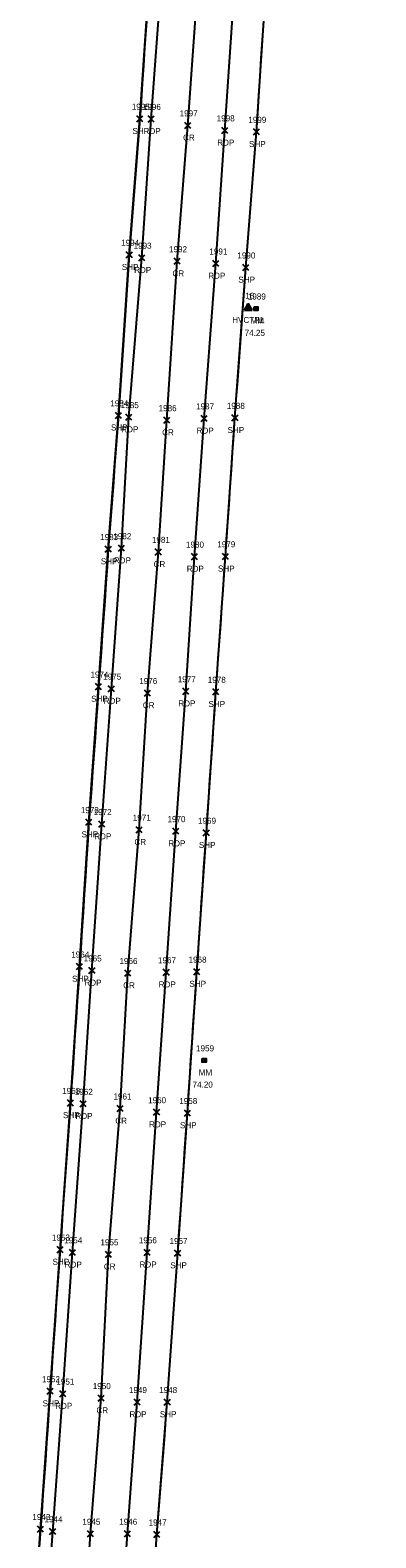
# Model space of a CAD drawing. Extents: x 1688195 to 1692013, y 424605 to 441234.
# Drawn here: x 1690595.7 to 1690709.9, y 436148.3 to 436646.5 of the extents above; entities that cross this region are included whole.
import ezdxf

# ---------------------------------------------------------------- set-up
doc = ezdxf.new("R2010")
doc.units = 0
for name, color, linetype in [('C_A', 7, 'Continuous'), ('C_I', 7, 'Continuous'), ('CPSM', 7, 'Continuous'), ('LSOGP', 7, 'Continuous'), ('P_A', 7, 'Continuous'), ('P_I', 7, 'Continuous'), ('P_TIC', 7, 'Continuous'), ('PET', 7, 'Continuous'), ('PRC', 7, 'Continuous'), ('PSP', 7, 'Continuous'), ('S_A', 7, 'Continuous'), ('S_C', 7, 'Continuous'), ('S_I', 7, 'Continuous'), ('SRM', 7, 'Continuous')]:
    doc.layers.add(name, color=color, linetype=linetype)

msp = doc.modelspace()

# ---------------------------------------------------------------- linework, layer by layer
at = {"layer": 'CPSM'}
for p, q in [((1690666.48, 436554.06), (1690667.73, 436556.22)), ((1690666.48, 436554.06), (1690667.73, 436554.78)), ((1690666.48, 436554.06), (1690668.98, 436554.06)), ((1690668.98, 436554.06), (1690667.73, 436556.22)), ((1690667.73, 436554.78), (1690667.73, 436556.22)), ((1690667.73, 436554.78), (1690667.73, 436554.78)), ((1690667.73, 436554.78), (1690668.98, 436554.06))]:
    msp.add_line(p, q, dxfattribs=at)
at = {"layer": 'LSOGP'}
for points in [[(1690634.29, 436652.37), (1690633.89, 436646.51), (1690633.5, 436640.66), (1690633.11, 436634.8), (1690632.72, 436628.94), (1690632.33, 436623.09), (1690631.94, 436617.23), (1690631.5, 436611.61), (1690631.06, 436606), (1690630.62, 436600.38), (1690630.18, 436594.76), (1690629.74, 436589.14), (1690629.3, 436583.53), (1690628.87, 436577.91), (1690628.43, 436572.29), (1690627.98, 436565.66), (1690627.53, 436559.03), (1690627.08, 436552.4), (1690626.63, 436545.77), (1690626.18, 436539.14), (1690625.73, 436532.51), (1690625.29, 436525.87), (1690624.84, 436519.24), (1690624.42, 436513.72), (1690624, 436508.19), (1690623.58, 436502.66), (1690623.17, 436497.13), (1690622.75, 436491.6), (1690622.33, 436486.08), (1690621.91, 436480.55), (1690621.49, 436475.02), (1690621.09, 436469.34), (1690620.69, 436463.66), (1690620.29, 436457.98), (1690619.89, 436452.3), (1690619.49, 436446.62), (1690619.09, 436440.94), (1690618.69, 436435.26), (1690618.29, 436429.58), (1690617.89, 436423.98), (1690617.49, 436418.38), (1690617.1, 436412.78), (1690616.7, 436407.18), (1690616.3, 436401.58), (1690615.9, 436395.98), (1690615.5, 436390.38), (1690615.1, 436384.78), (1690614.71, 436378.82), (1690614.32, 436372.85), (1690613.93, 436366.89), (1690613.54, 436360.92), (1690613.15, 436354.96), (1690612.76, 436348.99), (1690612.37, 436343.03), (1690611.61, 436331.43), (1690611.23, 436325.79), (1690610.85, 436320.16), (1690610.48, 436314.52), (1690610.1, 436308.89), (1690609.73, 436303.26), (1690609.35, 436297.62), (1690608.98, 436291.99), (1690608.55, 436285.93), (1690608.12, 436279.87), (1690607.69, 436273.81), (1690607.26, 436267.75), (1690606.83, 436261.7), (1690606.41, 436255.64), (1690605.98, 436249.58), (1690605.55, 436243.52), (1690605.14, 436237.67), (1690604.73, 436231.82), (1690604.32, 436225.97), (1690603.91, 436220.12), (1690603.5, 436214.27), (1690603.09, 436208.42), (1690602.68, 436202.58), (1690602.27, 436196.73), (1690601.88, 436191.03), (1690601.48, 436185.34), (1690601.08, 436179.65), (1690600.69, 436173.95), (1690600.29, 436168.26), (1690599.89, 436162.57), (1690599.5, 436156.87), (1690598.67, 436145.19)], [(1690637.08, 436143.21), (1690637.49, 436149.36), (1690637.93, 436154.83), (1690638.36, 436160.31), (1690638.8, 436165.78), (1690639.24, 436171.25), (1690639.67, 436176.72), (1690640.11, 436182.19), (1690640.54, 436187.66), (1690640.98, 436193.14), (1690641.41, 436199.29), (1690641.84, 436205.44), (1690642.27, 436211.6), (1690642.7, 436217.75), (1690643.12, 436223.91), (1690643.55, 436230.06), (1690643.98, 436236.21), (1690644.41, 436242.37), (1690644.81, 436248.15), (1690645.22, 436253.94), (1690645.62, 436259.72), (1690646.02, 436265.51), (1690646.42, 436271.29), (1690646.82, 436277.08), (1690647.22, 436282.86), (1690647.62, 436288.65), (1690648.01, 436294.49), (1690648.4, 436300.33), (1690648.79, 436306.17), (1690649.18, 436312.01), (1690649.57, 436317.85), (1690649.96, 436323.7), (1690650.35, 436329.54), (1690650.74, 436335.38), (1690651.14, 436341.11), (1690651.53, 436346.85), (1690651.92, 436352.59), (1690652.31, 436358.32), (1690652.7, 436364.06), (1690653.1, 436369.8), (1690653.49, 436375.53), (1690653.88, 436381.27), (1690654.27, 436387.09), (1690654.67, 436392.91), (1690655.07, 436398.74), (1690655.46, 436404.56), (1690655.86, 436410.38), (1690656.25, 436416.21), (1690656.65, 436422.03), (1690657.04, 436427.85), (1690657.44, 436433.45), (1690657.83, 436439.04), (1690658.22, 436444.64), (1690658.61, 436450.24), (1690659.01, 436455.83), (1690659.4, 436461.43), (1690659.79, 436467.02), (1690660.19, 436472.62), (1690660.58, 436478.34), (1690660.97, 436484.06), (1690661.37, 436489.79), (1690661.76, 436495.51), (1690662.16, 436501.23), (1690662.55, 436506.95), (1690662.94, 436512.68), (1690663.34, 436518.4), (1690663.78, 436524.61), (1690664.23, 436530.82), (1690664.68, 436537.03), (1690665.13, 436543.25), (1690665.57, 436549.46), (1690666.02, 436555.67), (1690666.47, 436561.88), (1690666.91, 436568.09), (1690667.35, 436573.69), (1690667.8, 436579.3), (1690668.24, 436584.9), (1690668.68, 436590.5), (1690669.12, 436596.1), (1690669.56, 436601.7), (1690670, 436607.3), (1690670.44, 436612.91), (1690670.84, 436619), (1690671.24, 436625.09), (1690671.64, 436631.19), (1690672.04, 436637.28), (1690672.44, 436643.37), (1690672.84, 436649.47)]]:
    msp.add_lwpolyline(points, dxfattribs=at)
at = {"layer": 'P_TIC'}
for points in [[(1690630.94, 436616.23), (1690632.94, 436618.23)], [(1690632.94, 436616.23), (1690630.94, 436618.23)], [(1690634.65, 436616.18), (1690636.65, 436618.18)], [(1690636.65, 436616.18), (1690634.65, 436618.18)], [(1690646.75, 436614.04), (1690648.75, 436616.04)], [(1690648.75, 436614.04), (1690646.75, 436616.04)], [(1690658.98, 436612.4), (1690660.98, 436614.4)], [(1690660.98, 436612.4), (1690658.98, 436614.4)], [(1690669.44, 436611.91), (1690671.44, 436613.91)], [(1690671.44, 436611.91), (1690669.44, 436613.91)], [(1690627.43, 436571.29), (1690629.43, 436573.29)], [(1690629.43, 436571.29), (1690627.43, 436573.29)], [(1690631.52, 436570.32), (1690633.52, 436572.32)], [(1690633.52, 436570.32), (1690631.52, 436572.32)], [(1690643.24, 436569.17), (1690645.24, 436571.17)], [(1690645.24, 436569.17), (1690643.24, 436571.17)], [(1690656.01, 436568.4), (1690658.01, 436570.4)], [(1690658.01, 436568.4), (1690656.01, 436570.4)], [(1690665.91, 436567.09), (1690667.91, 436569.09)], [(1690667.91, 436567.09), (1690665.91, 436569.09)], [(1690623.84, 436518.24), (1690625.84, 436520.24)], [(1690625.84, 436518.24), (1690623.84, 436520.24)], [(1690627.28, 436517.63), (1690629.28, 436519.63)], [(1690629.28, 436517.63), (1690627.28, 436519.63)], [(1690639.85, 436516.62), (1690641.85, 436518.62)], [(1690641.85, 436516.62), (1690639.85, 436518.62)], [(1690652.18, 436517.22), (1690654.18, 436519.22)], [(1690654.18, 436517.22), (1690652.18, 436519.22)], [(1690662.34, 436517.4), (1690664.34, 436519.4)], [(1690664.34, 436517.4), (1690662.34, 436519.4)], [(1690620.49, 436474.02), (1690622.49, 436476.02)], [(1690622.49, 436474.02), (1690620.49, 436476.02)], [(1690624.84, 436474.31), (1690626.84, 436476.31)], [(1690626.84, 436474.31), (1690624.84, 436476.31)], [(1690637.02, 436473.09), (1690639.02, 436475.09)], [(1690639.02, 436473.09), (1690637.02, 436475.09)], [(1690648.93, 436471.54), (1690650.93, 436473.54)], [(1690650.93, 436471.54), (1690648.93, 436473.54)], [(1690659.19, 436471.62), (1690661.19, 436473.62)], [(1690661.19, 436471.62), (1690659.19, 436473.62)], [(1690617.29, 436428.58), (1690619.29, 436430.58)], [(1690619.29, 436428.58), (1690617.29, 436430.58)], [(1690621.49, 436427.9), (1690623.49, 436429.9)], [(1690623.49, 436427.9), (1690621.49, 436429.9)], [(1690633.46, 436426.45), (1690635.46, 436428.45)], [(1690635.46, 436426.45), (1690633.46, 436428.45)], [(1690646.13, 436427.04), (1690648.13, 436429.04)], [(1690648.13, 436427.04), (1690646.13, 436429.04)], [(1690656.04, 436426.85), (1690658.04, 436428.85)], [(1690658.04, 436426.85), (1690656.04, 436428.85)], [(1690614.1, 436383.78), (1690616.1, 436385.78)], [(1690616.1, 436383.78), (1690614.1, 436385.78)], [(1690618.34, 436383.14), (1690620.34, 436385.14)], [(1690620.34, 436383.14), (1690618.34, 436385.14)], [(1690630.69, 436381.27), (1690632.69, 436383.27)], [(1690632.69, 436381.27), (1690630.69, 436383.27)], [(1690642.82, 436380.8), (1690644.82, 436382.8)], [(1690644.82, 436380.8), (1690642.82, 436382.8)], [(1690652.88, 436380.27), (1690654.88, 436382.27)], [(1690654.88, 436380.27), (1690652.88, 436382.27)], [(1690610.98, 436336.06), (1690612.98, 436338.06)], [(1690612.98, 436336.06), (1690610.98, 436338.06)], [(1690615.1, 436334.77), (1690617.1, 436336.77)], [(1690617.1, 436334.77), (1690615.1, 436336.77)], [(1690626.98, 436333.91), (1690628.98, 436335.91)], [(1690628.98, 436333.91), (1690626.98, 436335.91)], [(1690639.65, 436334.17), (1690641.65, 436336.17)], [(1690641.65, 436334.17), (1690639.65, 436336.17)], [(1690649.74, 436334.38), (1690651.74, 436336.38)], [(1690651.74, 436334.38), (1690649.74, 436336.38)], [(1690607.98, 436290.99), (1690609.98, 436292.99)], [(1690609.98, 436290.99), (1690607.98, 436292.99)], [(1690612.15, 436290.7), (1690614.15, 436292.7)], [(1690614.15, 436290.7), (1690612.15, 436292.7)], [(1690624.37, 436289.15), (1690626.37, 436291.15)], [(1690626.37, 436289.15), (1690624.37, 436291.15)], [(1690636.46, 436287.92), (1690638.46, 436289.92)], [(1690638.46, 436287.92), (1690636.46, 436289.92)], [(1690646.62, 436287.65), (1690648.62, 436289.65)], [(1690648.62, 436287.65), (1690646.62, 436289.65)], [(1690604.55, 436242.52), (1690606.55, 436244.52)], [(1690606.55, 436242.52), (1690604.55, 436244.52)], [(1690608.62, 436241.61), (1690610.62, 436243.61)], [(1690610.62, 436241.61), (1690608.62, 436243.61)], [(1690620.58, 436240.95), (1690622.58, 436242.95)], [(1690622.58, 436240.95), (1690620.58, 436242.95)], [(1690633.33, 436241.62), (1690635.33, 436243.62)], [(1690635.33, 436241.62), (1690633.33, 436243.62)], [(1690643.41, 436241.37), (1690645.41, 436243.37)], [(1690645.41, 436241.37), (1690643.41, 436243.37)], [(1690601.27, 436195.73), (1690603.27, 436197.73)], [(1690603.27, 436195.73), (1690601.27, 436197.73)], [(1690605.45, 436194.92), (1690607.45, 436196.92)], [(1690607.45, 436194.92), (1690605.45, 436196.92)], [(1690618.14, 436193.44), (1690620.14, 436195.44)], [(1690620.14, 436193.44), (1690618.14, 436195.44)], [(1690630, 436192.14), (1690632, 436194.14)], [(1690632, 436192.14), (1690630, 436194.14)], [(1690639.98, 436192.14), (1690641.98, 436194.14)], [(1690641.98, 436192.14), (1690639.98, 436194.14)], [(1690598.1, 436150.18), (1690600.1, 436152.18)], [(1690600.1, 436150.18), (1690598.1, 436152.18)], [(1690602.11, 436149.42), (1690604.11, 436151.42)], [(1690604.11, 436149.42), (1690602.11, 436151.42)], [(1690614.61, 436148.6), (1690616.61, 436150.6)], [(1690616.61, 436148.6), (1690614.61, 436150.6)], [(1690626.83, 436148.61), (1690628.83, 436150.61)], [(1690628.83, 436148.61), (1690626.83, 436150.61)], [(1690636.49, 436148.36), (1690638.49, 436150.36)], [(1690638.49, 436148.36), (1690636.49, 436150.36)]]:
    msp.add_lwpolyline(points, dxfattribs=at)
at = {"layer": 'PET'}
for points in [[(1690599.8, 436103.13), (1690603.11, 436150.42), (1690606.45, 436195.92), (1690609.62, 436242.61), (1690613.15, 436291.7), (1690616.1, 436335.77), (1690619.34, 436384.14), (1690622.49, 436428.9), (1690625.84, 436475.31), (1690628.28, 436518.63), (1690632.52, 436571.32), (1690635.65, 436617.18), (1690639.02, 436663.31), (1690642.46, 436711.88), (1690645.52, 436755.73), (1690649.02, 436803.75), (1690652.27, 436851.26), (1690655.23, 436898.72), (1690658.96, 436945.13), (1690661.93, 436991.78), (1690665.8, 437037.84), (1690668.55, 437085.38), (1690672.22, 437133.51), (1690675.32, 437180.59)], [(1690624.3, 436100.17), (1690627.83, 436149.61), (1690631, 436193.14), (1690634.33, 436242.62), (1690637.46, 436288.92), (1690640.65, 436335.17), (1690643.82, 436381.8), (1690647.13, 436428.04), (1690649.93, 436472.54), (1690653.18, 436518.22), (1690657.01, 436569.4), (1690659.98, 436613.4), (1690663.31, 436662.09), (1690666.73, 436708.73), (1690670, 436753.83), (1690673.18, 436800.78), (1690676.66, 436849.03), (1690679.84, 436896.21), (1690683.52, 436944.48), (1690686.54, 436988.83), (1690689.86, 437035.4), (1690693.25, 437082.57), (1690696.48, 437132.39), (1690699.66, 437177.7)]]:
    msp.add_lwpolyline(points, dxfattribs=at)
at = {"layer": 'PRC'}
msp.add_lwpolyline([(1690612.37, 436101.96), (1690615.61, 436149.6), (1690619.14, 436194.44), (1690621.58, 436241.95), (1690625.37, 436290.15), (1690627.98, 436334.91), (1690631.69, 436382.27), (1690634.46, 436427.45), (1690638.02, 436474.09), (1690640.85, 436517.62), (1690644.24, 436570.17), (1690647.75, 436615.04), (1690651.12, 436662.81), (1690654.54, 436710.08), (1690657.74, 436755.06), (1690660.75, 436802.55), (1690664.33, 436850.21), (1690667.58, 436897.29), (1690670.81, 436944.27), (1690673.92, 436990), (1690677.36, 437036.96), (1690680.4, 437083.81), (1690683.84, 437132.47), (1690687.9, 437179.25)], dxfattribs=at)
at = {"layer": 'PSP'}
for points in [[(1690595.68, 436103.23), (1690599.1, 436151.18), (1690602.27, 436196.73), (1690605.55, 436243.52), (1690608.98, 436291.99), (1690611.98, 436337.06), (1690615.1, 436384.78), (1690618.29, 436429.58), (1690621.49, 436475.02), (1690624.84, 436519.24), (1690628.43, 436572.29), (1690631.94, 436617.23), (1690635.07, 436664.09), (1690638.1, 436712.12), (1690641.49, 436756.88), (1690644.68, 436803.77), (1690648.2, 436852.63), (1690651.28, 436898.94), (1690654.63, 436946.33), (1690657.71, 436992.3), (1690661.08, 437038.52), (1690664.37, 437085.75), (1690667.55, 437134.28), (1690670.88, 437180.54)], [(1690634.23, 436100.1), (1690637.49, 436149.36), (1690640.98, 436193.14), (1690644.41, 436242.37), (1690647.62, 436288.65), (1690650.74, 436335.38), (1690653.88, 436381.27), (1690657.04, 436427.85), (1690660.19, 436472.62), (1690663.34, 436518.4), (1690666.91, 436568.09), (1690670.44, 436612.91), (1690673.64, 436661.65), (1690677.16, 436708.74), (1690680.36, 436753.14), (1690683.38, 436799.8), (1690686.78, 436848.43), (1690688.77, 436896.68), (1690693.3, 436942.76), (1690696.54, 436989.07), (1690699.73, 437035.52), (1690703.25, 437082.34), (1690706.73, 437130.77), (1690709.86, 437177.48)]]:
    msp.add_lwpolyline(points, dxfattribs=at)
at = {"layer": 'SRM'}
for points in [[(1690669.66, 436555.14), (1690670.91, 436555.14), (1690670.91, 436553.89), (1690669.66, 436553.89)], [(1690652.54, 436306.71), (1690653.79, 436306.71), (1690653.79, 436305.46), (1690652.54, 436305.46)]]:
    msp.add_lwpolyline(points, close=True, dxfattribs=at)
for centre in [(1690670.28, 436554.52), (1690653.17, 436306.08)]:
    msp.add_circle(centre, 0.0833, dxfattribs=at)

# ---------------------------------------------------------------- texts
at = {"layer": 'C_A'}
msp.add_text('HVCTRL', height=2, dxfattribs=at).set_placement((1690662.42, 436549.78))
at = {"layer": 'C_I'}
msp.add_text('16', height=2, dxfattribs=at).set_placement((1690666.77, 436557.78))
at = {"layer": 'P_A'}
for s, p in [('SHP', (1690629.47, 436612.23)), ('RDP', (1690633.14, 436612.18)), ('CR', (1690646.18, 436610.04)), ('RDP', (1690657.47, 436608.4)), ('SHP', (1690667.98, 436607.91)), ('SHP', (1690625.96, 436567.29)), ('RDP', (1690630.01, 436566.32)), ('CR', (1690642.68, 436565.17)), ('RDP', (1690654.49, 436564.4)), ('SHP', (1690664.45, 436563.09)), ('SHP', (1690622.37, 436514.24)), ('RDP', (1690625.77, 436513.63)), ('CR', (1690639.28, 436512.62)), ('RDP', (1690650.67, 436513.22)), ('SHP', (1690660.87, 436513.4)), ('RDP', (1690623.32, 436470.31)), ('SHP', (1690619.03, 436470.02)), ('CR', (1690636.45, 436469.09)), ('RDP', (1690647.41, 436467.54)), ('SHP', (1690657.72, 436467.62)), ('SHP', (1690615.83, 436424.58)), ('RDP', (1690619.98, 436423.9)), ('CR', (1690632.89, 436422.45)), ('RDP', (1690644.62, 436423.04)), ('SHP', (1690654.58, 436422.85)), ('SHP', (1690612.64, 436379.78)), ('RDP', (1690616.83, 436379.14)), ('CR', (1690630.12, 436377.27)), ('RDP', (1690641.31, 436376.8)), ('SHP', (1690651.41, 436376.27)), ('SHP', (1690609.52, 436332.06)), ('RDP', (1690613.59, 436330.77)), ('CR', (1690626.41, 436329.91)), ('RDP', (1690638.14, 436330.17)), ('SHP', (1690648.28, 436330.38)), ('SHP', (1690606.51, 436286.99)), ('RDP', (1690610.64, 436286.7)), ('CR', (1690623.8, 436285.15)), ('RDP', (1690634.95, 436283.92)), ('SHP', (1690645.16, 436283.65)), ('SHP', (1690603.08, 436238.52)), ('RDP', (1690607.1, 436237.61)), ('CR', (1690620.02, 436236.95)), ('RDP', (1690631.82, 436237.62)), ('SHP', (1690641.95, 436237.37)), ('SHP', (1690599.81, 436191.73)), ('RDP', (1690603.94, 436190.92)), ('CR', (1690617.57, 436189.44)), ('RDP', (1690628.48, 436188.14)), ('SHP', (1690638.51, 436188.14))]:
    msp.add_text(s, height=2, dxfattribs=at).set_placement(p)
at = {"layer": 'P_I'}
for s, p in [('1995', (1690629.25, 436620.23)), ('1996', (1690632.9, 436620.18)), ('1997', (1690645.05, 436618.04)), ('1998', (1690657.29, 436616.4)), ('1999', (1690667.74, 436615.91)), ('1994', (1690625.73, 436575.29)), ('1993', (1690629.83, 436574.32)), ('1992', (1690641.55, 436573.17)), ('1991', (1690654.88, 436572.4)), ('1990', (1690664.13, 436571.09)), ('1984', (1690622.14, 436522.24)), ('1985', (1690625.59, 436521.63)), ('1986', (1690638.1, 436520.62)), ('1987', (1690650.48, 436521.22)), ('1988', (1690660.64, 436521.4)), ('1983', (1690618.8, 436478.02)), ('1982', (1690623.14, 436478.31)), ('1981', (1690635.89, 436477.09)), ('1980', (1690647.15, 436475.54)), ('1979', (1690657.49, 436475.62)), ('1974', (1690615.6, 436432.58)), ('1975', (1690619.8, 436431.9)), ('1976', (1690631.71, 436430.45)), ('1977', (1690644.44, 436431.04)), ('1978', (1690654.35, 436430.85)), ('1973', (1690612.41, 436387.78)), ('1972', (1690616.65, 436387.14)), ('1971', (1690629.56, 436385.27)), ('1970', (1690641.04, 436384.8)), ('1969', (1690651.13, 436384.27)), ('1964', (1690609.24, 436340.06)), ('1965', (1690613.36, 436338.77)), ('1966', (1690625.18, 436337.91)), ('1967', (1690637.91, 436338.17)), ('1968', (1690648, 436338.38)), ('1963', (1690606.24, 436294.99)), ('1962', (1690610.41, 436294.7)), ('1961', (1690623.2, 436293.15)), ('1960', (1690634.64, 436291.92)), ('1958', (1690644.93, 436291.65)), ('1953', (1690602.86, 436246.52)), ('1954', (1690606.92, 436245.61)), ('1955', (1690618.89, 436244.95)), ('1956', (1690631.58, 436245.62)), ('1957', (1690641.72, 436245.37)), ('1952', (1690599.58, 436199.73)), ('1951', (1690604.33, 436198.92)), ('1950', (1690616.36, 436197.44)), ('1949', (1690628.3, 436196.14)), ('1948', (1690638.28, 436196.14)), ('1943', (1690596.41, 436154.18)), ('1944', (1690600.41, 436153.42)), ('1945', (1690612.92, 436152.6)), ('1946', (1690625.09, 436152.61)), ('1947', (1690634.8, 436152.36))]:
    msp.add_text(s, height=2, dxfattribs=at).set_placement(p)
at = {"layer": 'S_A'}
for p in [(1690668.47, 436549.52), (1690651.36, 436301.08)]:
    msp.add_text('MM', height=2, dxfattribs=at).set_placement(p)
at = {"layer": 'S_C'}
for s, p in [('74.25', (1690666.54, 436545.52)), ('74.20', (1690649.33, 436297.08))]:
    msp.add_text(s, height=2, dxfattribs=at).set_placement(p)
at = {"layer": 'S_I'}
for s, p in [('1989', (1690667.58, 436557.52)), ('1959', (1690650.47, 436309.08))]:
    msp.add_text(s, height=2, dxfattribs=at).set_placement(p)

doc.saveas('drawing.dxf')
